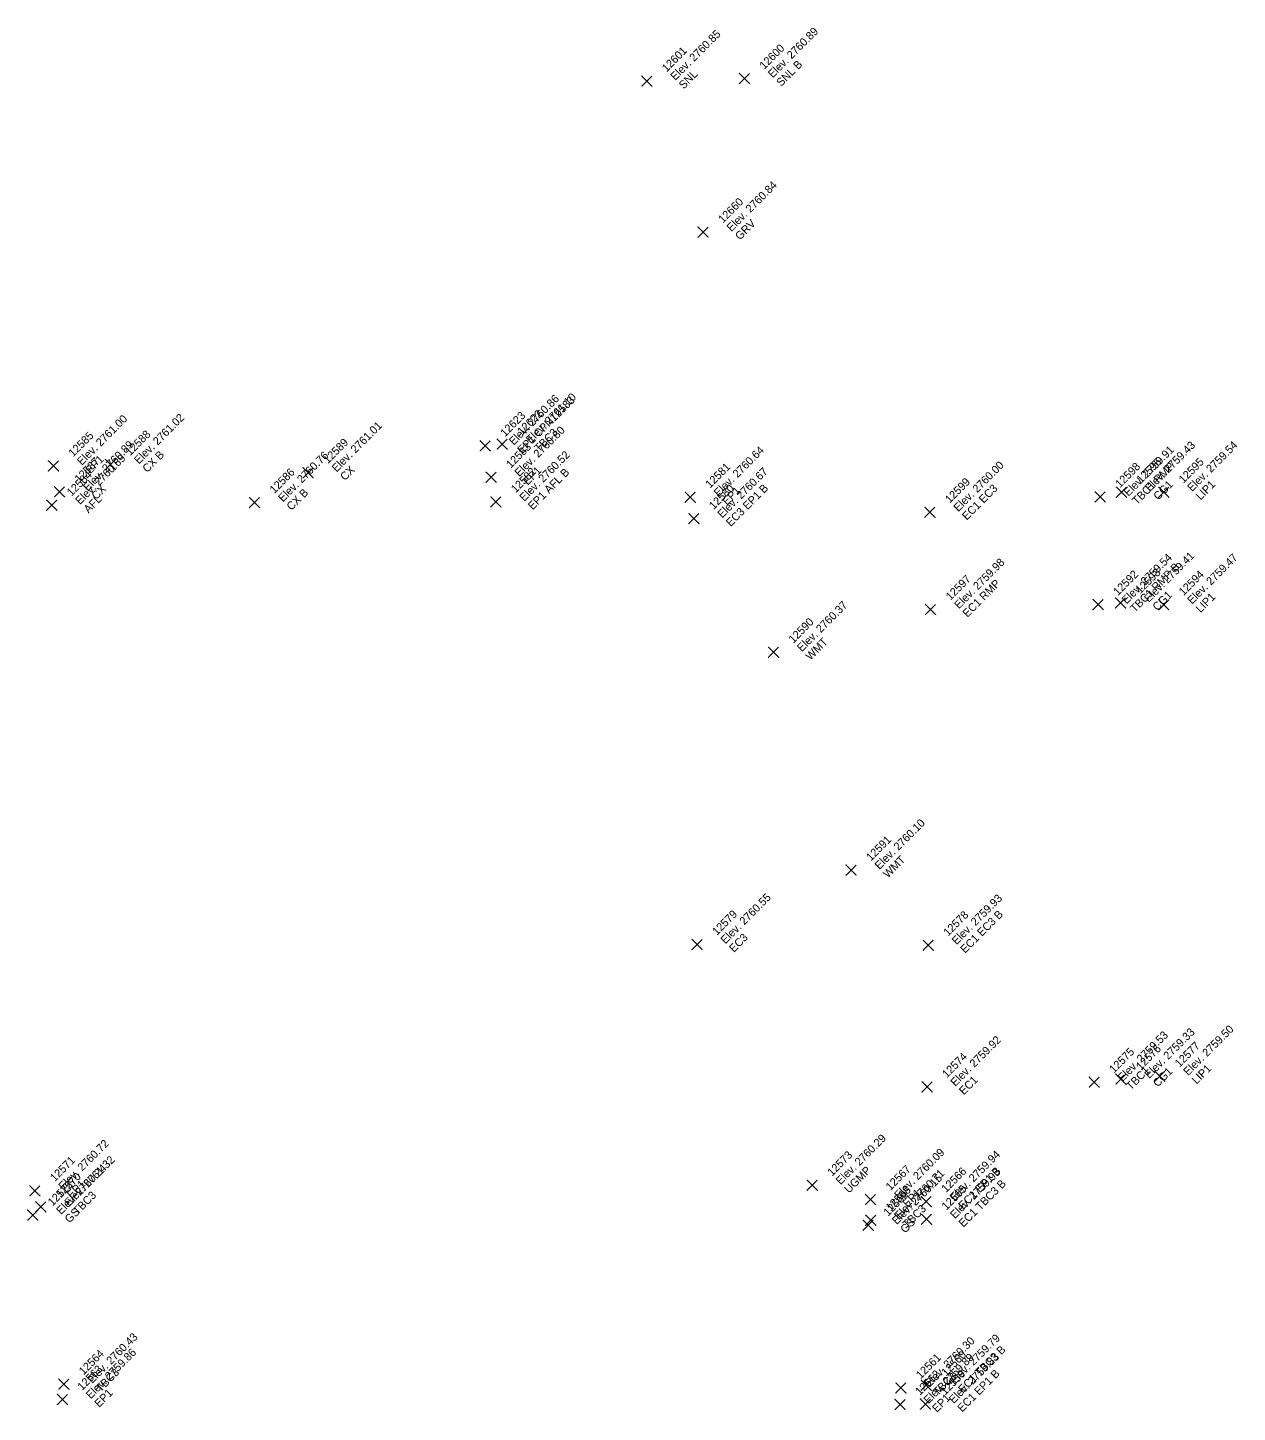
# Model space of a CAD drawing. Extents: x 2493999 to 2503109, y 700767 to 706646.
# Drawn here: x 2502218.72 to 2502254.99, y 702477 to 702518.52 of the extents above; entities that cross this region are included whole.
import ezdxf

# ---------------------------------------------------------------- set-up
doc = ezdxf.new("R2010")
doc.units = 0
doc.layers.add('ALG_CL_BLUE_Horiz', color=7, linetype='Continuous')
doc.layers.add('DES_SURFACE_Existing-Ground', color=7, linetype='Continuous')

msp = doc.modelspace()

# ---------------------------------------------------------------- linework, layer by layer
at = {"layer": 'ALG_CL_BLUE_Horiz'}
for points in [[(2502240.21, 702517), (2502240.06, 702517.15), (2502240.21, 702517), (2502240.06, 702516.85), (2502240.21, 702517), (2502240.36, 702516.85), (2502240.21, 702517), (2502240.36, 702517.15)], [(2502237.286, 702516.922), (2502237.136, 702517.072), (2502237.286, 702516.922), (2502237.136, 702516.772), (2502237.286, 702516.922), (2502237.436, 702516.772), (2502237.286, 702516.922), (2502237.436, 702517.072)], [(2502238.974, 702512.391), (2502238.824, 702512.541), (2502238.974, 702512.391), (2502238.824, 702512.241), (2502238.974, 702512.391), (2502239.124, 702512.241), (2502238.974, 702512.391), (2502239.124, 702512.541)], [(2502232.44, 702505.983), (2502232.29, 702506.133), (2502232.44, 702505.983), (2502232.29, 702505.833), (2502232.44, 702505.983), (2502232.59, 702505.833), (2502232.44, 702505.983), (2502232.59, 702506.133)], [(2502232.951, 702506.034), (2502232.801, 702506.184), (2502232.951, 702506.034), (2502232.801, 702505.884), (2502232.951, 702506.034), (2502233.101, 702505.884), (2502232.951, 702506.034), (2502233.101, 702506.184)], [(2502219.489, 702505.38), (2502219.339, 702505.53), (2502219.489, 702505.38), (2502219.339, 702505.23), (2502219.489, 702505.38), (2502219.639, 702505.23), (2502219.489, 702505.38), (2502219.639, 702505.53)], [(2502221.198, 702505.419), (2502221.048, 702505.569), (2502221.198, 702505.419), (2502221.048, 702505.269), (2502221.198, 702505.419), (2502221.348, 702505.269), (2502221.198, 702505.419), (2502221.348, 702505.569)], [(2502227.128, 702505.177), (2502226.978, 702505.327), (2502227.128, 702505.177), (2502226.978, 702505.027), (2502227.128, 702505.177), (2502227.278, 702505.027), (2502227.128, 702505.177), (2502227.278, 702505.327)], [(2502232.612, 702505.041), (2502232.462, 702505.191), (2502232.612, 702505.041), (2502232.462, 702504.891), (2502232.612, 702505.041), (2502232.762, 702504.891), (2502232.612, 702505.041), (2502232.762, 702505.191)], [(2502219.671, 702504.606), (2502219.521, 702504.756), (2502219.671, 702504.606), (2502219.521, 702504.456), (2502219.671, 702504.606), (2502219.821, 702504.456), (2502219.671, 702504.606), (2502219.821, 702504.756)], [(2502251.518, 702504.591), (2502251.368, 702504.741), (2502251.518, 702504.591), (2502251.368, 702504.441), (2502251.518, 702504.591), (2502251.668, 702504.441), (2502251.518, 702504.591), (2502251.668, 702504.741)], [(2502252.786, 702504.592), (2502252.636, 702504.742), (2502252.786, 702504.592), (2502252.636, 702504.442), (2502252.786, 702504.592), (2502252.936, 702504.442), (2502252.786, 702504.592), (2502252.936, 702504.742)], [(2502219.438, 702504.202), (2502219.288, 702504.352), (2502219.438, 702504.202), (2502219.288, 702504.052), (2502219.438, 702504.202), (2502219.588, 702504.052), (2502219.438, 702504.202), (2502219.588, 702504.352)], [(2502225.521, 702504.283), (2502225.371, 702504.433), (2502225.521, 702504.283), (2502225.371, 702504.133), (2502225.521, 702504.283), (2502225.671, 702504.133), (2502225.521, 702504.283), (2502225.671, 702504.433)], [(2502232.758, 702504.3), (2502232.608, 702504.45), (2502232.758, 702504.3), (2502232.608, 702504.15), (2502232.758, 702504.3), (2502232.908, 702504.15), (2502232.758, 702504.3), (2502232.908, 702504.45)], [(2502238.587, 702504.44), (2502238.437, 702504.59), (2502238.587, 702504.44), (2502238.437, 702504.29), (2502238.587, 702504.44), (2502238.737, 702504.29), (2502238.587, 702504.44), (2502238.737, 702504.59)], [(2502250.88, 702504.453), (2502250.73, 702504.603), (2502250.88, 702504.453), (2502250.73, 702504.303), (2502250.88, 702504.453), (2502251.03, 702504.303), (2502250.88, 702504.453), (2502251.03, 702504.603)], [(2502238.697, 702503.799), (2502238.547, 702503.949), (2502238.697, 702503.799), (2502238.547, 702503.649), (2502238.697, 702503.799), (2502238.847, 702503.649), (2502238.697, 702503.799), (2502238.847, 702503.949)], [(2502245.777, 702503.992), (2502245.627, 702504.142), (2502245.777, 702503.992), (2502245.627, 702503.842), (2502245.777, 702503.992), (2502245.927, 702503.842), (2502245.777, 702503.992), (2502245.927, 702504.142)], [(2502250.819, 702501.221), (2502250.669, 702501.371), (2502250.819, 702501.221), (2502250.669, 702501.071), (2502250.819, 702501.221), (2502250.969, 702501.071), (2502250.819, 702501.221), (2502250.969, 702501.371)], [(2502251.491, 702501.274), (2502251.341, 702501.424), (2502251.491, 702501.274), (2502251.341, 702501.124), (2502251.491, 702501.274), (2502251.641, 702501.124), (2502251.491, 702501.274), (2502251.641, 702501.424)], [(2502252.787, 702501.218), (2502252.637, 702501.368), (2502252.787, 702501.218), (2502252.637, 702501.068), (2502252.787, 702501.218), (2502252.937, 702501.068), (2502252.787, 702501.218), (2502252.937, 702501.368)], [(2502245.797, 702501.078), (2502245.647, 702501.228), (2502245.797, 702501.078), (2502245.647, 702500.928), (2502245.797, 702501.078), (2502245.947, 702500.928), (2502245.797, 702501.078), (2502245.947, 702501.228)], [(2502241.085, 702499.793), (2502240.935, 702499.943), (2502241.085, 702499.793), (2502240.935, 702499.643), (2502241.085, 702499.793), (2502241.235, 702499.643), (2502241.085, 702499.793), (2502241.235, 702499.943)], [(2502243.412, 702493.261), (2502243.262, 702493.411), (2502243.412, 702493.261), (2502243.262, 702493.111), (2502243.412, 702493.261), (2502243.562, 702493.111), (2502243.412, 702493.261), (2502243.562, 702493.411)], [(2502238.792, 702491.029), (2502238.642, 702491.179), (2502238.792, 702491.029), (2502238.642, 702490.879), (2502238.792, 702491.029), (2502238.942, 702490.879), (2502238.792, 702491.029), (2502238.942, 702491.179)], [(2502245.727, 702491.004), (2502245.577, 702491.154), (2502245.727, 702491.004), (2502245.577, 702490.854), (2502245.727, 702491.004), (2502245.877, 702490.854), (2502245.727, 702491.004), (2502245.877, 702491.154)], [(2502245.689, 702486.756), (2502245.539, 702486.906), (2502245.689, 702486.756), (2502245.539, 702486.606), (2502245.689, 702486.756), (2502245.839, 702486.606), (2502245.689, 702486.756), (2502245.839, 702486.906)], [(2502250.702, 702486.9), (2502250.552, 702487.05), (2502250.702, 702486.9), (2502250.552, 702486.75), (2502250.702, 702486.9), (2502250.852, 702486.75), (2502250.702, 702486.9), (2502250.852, 702487.05)], [(2502251.503, 702486.991), (2502251.353, 702487.141), (2502251.503, 702486.991), (2502251.353, 702486.841), (2502251.503, 702486.991), (2502251.653, 702486.841), (2502251.503, 702486.991), (2502251.653, 702487.141)], [(2502252.668, 702487.077), (2502252.518, 702487.227), (2502252.668, 702487.077), (2502252.518, 702486.927), (2502252.668, 702487.077), (2502252.818, 702486.927), (2502252.668, 702487.077), (2502252.818, 702487.227)], [(2502242.245, 702483.806), (2502242.095, 702483.956), (2502242.245, 702483.806), (2502242.095, 702483.656), (2502242.245, 702483.806), (2502242.395, 702483.656), (2502242.245, 702483.806), (2502242.395, 702483.956)], [(2502218.935, 702483.645), (2502218.785, 702483.795), (2502218.935, 702483.645), (2502218.785, 702483.495), (2502218.935, 702483.645), (2502219.085, 702483.495), (2502218.935, 702483.645), (2502219.085, 702483.795)], [(2502243.997, 702483.382), (2502243.847, 702483.532), (2502243.997, 702483.382), (2502243.847, 702483.232), (2502243.997, 702483.382), (2502244.147, 702483.232), (2502243.997, 702483.382), (2502244.147, 702483.532)], [(2502219.111, 702483.159), (2502218.961, 702483.309), (2502219.111, 702483.159), (2502218.961, 702483.009), (2502219.111, 702483.159), (2502219.261, 702483.009), (2502219.111, 702483.159), (2502219.261, 702483.309)], [(2502245.667, 702483.318), (2502245.517, 702483.468), (2502245.667, 702483.318), (2502245.517, 702483.168), (2502245.667, 702483.318), (2502245.817, 702483.168), (2502245.667, 702483.318), (2502245.817, 702483.468)], [(2502218.867, 702482.913), (2502218.717, 702483.063), (2502218.867, 702482.913), (2502218.717, 702482.763), (2502218.867, 702482.913), (2502219.017, 702482.763), (2502218.867, 702482.913), (2502219.017, 702483.063)], [(2502243.928, 702482.61), (2502243.778, 702482.76), (2502243.928, 702482.61), (2502243.778, 702482.46), (2502243.928, 702482.61), (2502244.078, 702482.46), (2502243.928, 702482.61), (2502244.078, 702482.76)], [(2502243.999, 702482.756), (2502243.849, 702482.906), (2502243.999, 702482.756), (2502243.849, 702482.606), (2502243.999, 702482.756), (2502244.149, 702482.606), (2502243.999, 702482.756), (2502244.149, 702482.906)], [(2502245.675, 702482.789), (2502245.525, 702482.939), (2502245.675, 702482.789), (2502245.525, 702482.639), (2502245.675, 702482.789), (2502245.825, 702482.639), (2502245.675, 702482.789), (2502245.825, 702482.939)], [(2502219.801, 702477.846), (2502219.651, 702477.996), (2502219.801, 702477.846), (2502219.651, 702477.696), (2502219.801, 702477.846), (2502219.951, 702477.696), (2502219.801, 702477.846), (2502219.951, 702477.996)], [(2502244.905, 702477.729), (2502244.755, 702477.879), (2502244.905, 702477.729), (2502244.755, 702477.579), (2502244.905, 702477.729), (2502245.055, 702477.579), (2502244.905, 702477.729), (2502245.055, 702477.879)], [(2502245.663, 702477.812), (2502245.513, 702477.962), (2502245.663, 702477.812), (2502245.513, 702477.662), (2502245.663, 702477.812), (2502245.813, 702477.662), (2502245.663, 702477.812), (2502245.813, 702477.962)], [(2502219.756, 702477.383), (2502219.606, 702477.533), (2502219.756, 702477.383), (2502219.606, 702477.233), (2502219.756, 702477.383), (2502219.906, 702477.233), (2502219.756, 702477.383), (2502219.906, 702477.533)], [(2502244.88, 702477.234), (2502244.73, 702477.384), (2502244.88, 702477.234), (2502244.73, 702477.084), (2502244.88, 702477.234), (2502245.03, 702477.084), (2502244.88, 702477.234), (2502245.03, 702477.384)], [(2502245.638, 702477.246), (2502245.488, 702477.396), (2502245.638, 702477.246), (2502245.488, 702477.096), (2502245.638, 702477.246), (2502245.788, 702477.096), (2502245.638, 702477.246), (2502245.788, 702477.396)]]:
    msp.add_lwpolyline(points, dxfattribs=at)

# ---------------------------------------------------------------- texts
at = {"layer": 'DES_SURFACE_Existing-Ground'}
for s, p in [('Elev. 2760.85', (2502238.135, 702516.922)), ('Elev. 2760.89', (2502241.059, 702517)), ('12600', (2502240.804, 702517.255)), ('12601', (2502237.88, 702517.177)), ('SNL B', (2502241.313, 702516.745)), ('SNL', (2502238.389, 702516.667)), ('Elev. 2760.84', (2502239.823, 702512.391)), ('12660', (2502239.568, 702512.646)), ('GRV', (2502240.077, 702512.136)), ('Elev. 2760.86', (2502233.289, 702505.983)), ('EP1 CPN12583', (2502233.543, 702505.728)), ('Elev. 2761.10', (2502233.8, 702506.034)), ('Elev. 2761.00', (2502220.338, 702505.38)), ('Elev. 2761.02', (2502222.047, 702505.419)), ('12623', (2502233.034, 702506.238)), ('12622', (2502233.545, 702506.289)), ('12585', (2502220.083, 702505.635)), ('12588', (2502221.792, 702505.674)), ('Elev. 2761.01', (2502227.977, 702505.177)), ('Elev. 2760.80', (2502233.461, 702505.041)), ('TBC3', (2502234.054, 702505.779)), ('Elev. 2760.89', (2502220.52, 702504.606)), ('12589', (2502227.722, 702505.432)), ('12583', (2502233.206, 702505.296)), ('Elev. 2760.64', (2502239.436, 702504.44)), ('Elev. 2759.91', (2502251.729, 702504.453)), ('Elev. 2759.43', (2502252.367, 702504.591)), ('Elev. 2759.54', (2502253.635, 702504.592)), ('Elev. 2760.69', (2502220.287, 702504.202)), ('12587', (2502220.265, 702504.861)), ('EP1', (2502220.592, 702505.125)), ('CX B', (2502222.301, 702505.164)), ('Elev. 2760.76', (2502226.37, 702504.283)), ('Elev. 2760.52', (2502233.607, 702504.3)), ('Elev. 2760.00', (2502246.626, 702503.992)), ('12596', (2502252.112, 702504.846)), ('12595', (2502253.38, 702504.847)), ('12584', (2502220.032, 702504.457)), ('12586', (2502226.115, 702504.538)), ('CX', (2502228.231, 702504.922)), ('12582', (2502233.352, 702504.555)), ('EP1', (2502233.715, 702504.786)), ('EP1 AFL B', (2502233.861, 702504.045)), ('12581', (2502239.181, 702504.695)), ('Elev. 2760.67', (2502239.546, 702503.799)), ('12598', (2502251.474, 702504.708)), ('TBC1 RMP', (2502251.983, 702504.198)), ('CX', (2502220.774, 702504.351)), ('CX B', (2502226.624, 702504.028)), ('12580', (2502239.291, 702504.054)), ('EP1', (2502239.69, 702504.185)), ('EC3 EP1 B', (2502239.8, 702503.544)), ('12599', (2502246.371, 702504.247)), ('EC1 EC3', (2502246.88, 702503.737)), ('CG1', (2502252.621, 702504.336)), ('LIP1', (2502253.889, 702504.337)), ('AFL', (2502220.541, 702503.947)), ('Elev. 2759.54', (2502251.668, 702501.221)), ('Elev. 2759.41', (2502252.34, 702501.274)), ('Elev. 2759.47', (2502253.636, 702501.218)), ('Elev. 2759.98', (2502246.646, 702501.078)), ('12592', (2502251.413, 702501.476)), ('TBC1 RMP B', (2502251.922, 702500.966)), ('12593', (2502252.085, 702501.529)), ('12594', (2502253.381, 702501.473)), ('12597', (2502246.391, 702501.333)), ('EC1 RMP', (2502246.9, 702500.823)), ('CG1', (2502252.594, 702501.019)), ('LIP1', (2502253.89, 702500.963)), ('Elev. 2760.37', (2502241.934, 702499.793)), ('12590', (2502241.679, 702500.048)), ('WMT', (2502242.188, 702499.538)), ('Elev. 2760.10', (2502244.261, 702493.261)), ('12591', (2502244.006, 702493.516)), ('WMT', (2502244.515, 702493.006)), ('Elev. 2760.55', (2502239.641, 702491.029)), ('Elev. 2759.93', (2502246.576, 702491.004)), ('12579', (2502239.386, 702491.284)), ('12578', (2502246.321, 702491.259)), ('EC1 EC3 B', (2502246.83, 702490.749)), ('EC3', (2502239.895, 702490.774)), ('Elev. 2759.33', (2502252.352, 702486.991)), ('Elev. 2759.50', (2502253.517, 702487.077)), ('Elev. 2759.92', (2502246.538, 702486.756)), ('Elev. 2759.53', (2502251.551, 702486.9)), ('12577', (2502253.262, 702487.332)), ('12574', (2502246.283, 702487.011)), ('12575', (2502251.296, 702487.155)), ('12576', (2502252.097, 702487.246)), ('TBC1', (2502251.805, 702486.645)), ('CG1', (2502252.606, 702486.736)), ('LIP1', (2502253.771, 702486.822)), ('EC1', (2502246.792, 702486.501)), ('Elev. 2760.72', (2502219.784, 702483.645)), ('Elev. 2760.29', (2502243.094, 702483.806)), ('12573', (2502242.839, 702484.061)), ('Elev. 2760.09', (2502244.846, 702483.382)), ('Elev. 2759.94', (2502246.516, 702483.318)), ('12571', (2502219.529, 702483.9)), ('Elev. 2760.24', (2502219.716, 702482.913)), ('Elev. 2761.32', (2502219.96, 702483.159)), ('UGMP', (2502243.348, 702483.551)), ('12567', (2502244.591, 702483.637)), ('12566', (2502246.261, 702483.573)), ('EC1 EP1 B', (2502246.77, 702483.063)), ('12572', (2502219.461, 702483.168)), ('12570', (2502219.705, 702483.414)), ('EP1', (2502220.038, 702483.39)), ('Elev. 2760.15', (2502244.777, 702482.61)), ('Elev. 2760.71', (2502244.848, 702482.756)), ('Elev. 2759.93', (2502246.524, 702482.789)), ('EC1 TBC3 B', (2502246.778, 702482.534)), ('TBC3', (2502220.214, 702482.904)), ('12569', (2502244.522, 702482.865)), ('12568', (2502244.593, 702483.011)), ('EP1', (2502245.1, 702483.127)), ('12565', (2502246.269, 702483.044)), ('GS', (2502219.97, 702482.658)), ('TBC3', (2502245.102, 702482.501)), ('GS', (2502245.031, 702482.355)), ('Elev. 2760.43', (2502220.65, 702477.846)), ('Elev. 2760.30', (2502245.754, 702477.729)), ('Elev. 2759.79', (2502246.512, 702477.812)), ('EC1 TBC3 B', (2502246.766, 702477.557)), ('12564', (2502220.395, 702478.101)), ('Elev. 2759.86', (2502220.605, 702477.383)), ('12561', (2502245.499, 702477.984)), ('Elev. 2759.89', (2502245.729, 702477.234)), ('12560', (2502246.257, 702478.067)), ('Elev. 2759.83', (2502246.487, 702477.246)), ('12563', (2502220.35, 702477.638)), ('TBC3', (2502220.904, 702477.591)), ('12562', (2502245.474, 702477.489)), ('TBC3', (2502246.008, 702477.474)), ('12559', (2502246.232, 702477.501)), ('EC1 EP1 B', (2502246.741, 702476.991)), ('EP1', (2502220.859, 702477.128)), ('EP1', (2502245.983, 702476.979))]:
    msp.add_text(s, height=0.24, rotation=45, dxfattribs=at).set_placement(p)

doc.saveas('drawing.dxf')
